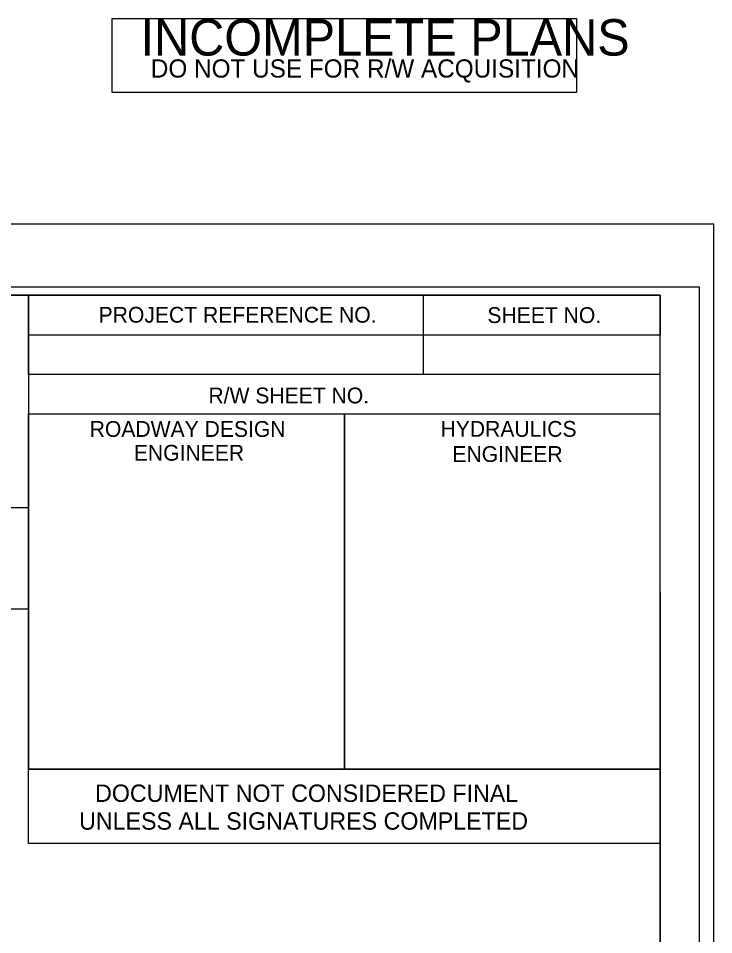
# Model space of a CAD drawing. Extents: x 2044275 to 2045958, y 759228 to 760388.
# Drawn here: x 2045738.1 to 2045958.4, y 760098.4 to 760388.4 of the extents above; entities that cross this region are included whole.
import ezdxf

# ---------------------------------------------------------------- set-up
doc = ezdxf.new("R2010")
doc.units = 0
for name, color, linetype in [('Old_Level_4', 7, 'Continuous'), ('Sheet Cutting Line CELL', 7, 'Continuous'), ('Sheet Plan CELL', 7, 'Continuous'), ('Sheet Plot Border Inside CELL', 7, 'Continuous'), ('Sheet Plot Border Outside CELL', 7, 'Continuous'), ('Sheet Sticker Exception Certification CELL', 7, 'Continuous'), ('Sheet Sticker Incomplete CELL', 7, 'Continuous')]:
    doc.layers.add(name, color=color, linetype=linetype)

msp = doc.modelspace()

# ---------------------------------------------------------------- linework, layer by layer
at = {"layer": 'Old_Level_4'}
for p, q in [((2045543.25, 760233.57), (2045741.31, 760233.57)), ((2045543.25, 760233.57), (2045741.31, 760233.57)), ((2045741.31, 760233.57), (2045741.31, 760201.37)), ((2045741.31, 760201.37), (2045543.25, 760201.37))]:
    msp.add_line(p, q, dxfattribs=at)
at = {"layer": 'Sheet Cutting Line CELL'}
msp.add_line((2045958.35, 760323.28), (2044274.85, 760323.28), dxfattribs=at)
at = {"layer": 'Sheet Plan CELL'}
for p, q in [((2045866.32, 760300.73), (2045866.37, 760275.73)), ((2045741.29, 760288.26), (2045941.34, 760288.25)), ((2045741.3, 760275.72), (2045941.34, 760275.75)), ((2045741.3, 760275.72), (2045941.34, 760275.75)), ((2045741.3, 760275.72), (2045741.3, 760263.23)), ((2045841.35, 760263.23), (2045841.37, 760150.77))]:
    msp.add_line(p, q, dxfattribs=at)
for points in [[(2044441.34, 759250.8), (2044441.32, 760300.77), (2045741.3, 760300.81), (2045741.32, 760150.75), (2045941.35, 760150.73), (2045941.35, 759250.8)], [(2045941.38, 760300.8), (2044441.34, 760300.8), (2044441.34, 759250.8), (2045941.35, 759250.8)], [(2045741.3, 760300.81), (2045941.38, 760300.8), (2045941.34, 760275.75), (2045741.3, 760275.72)], [(2045741.3, 760263.23), (2045841.35, 760263.23), (2045841.35, 760150.72), (2045741.32, 760150.75)], [(2045841.35, 760263.23), (2045941.34, 760263.25), (2045941.35, 760150.73), (2045841.35, 760150.72)]]:
    msp.add_lwpolyline(points, close=True, dxfattribs=at)
at = {"layer": 'Sheet Plot Border Inside CELL'}
msp.add_lwpolyline([(2044287.85, 759248.28), (2045953.84, 759248.3), (2045953.85, 760303.28), (2044287.85, 760303.28)], close=True, dxfattribs=at)
at = {"layer": 'Sheet Plot Border Outside CELL'}
msp.add_lwpolyline([(2044274.85, 759228.28), (2045958.35, 759228.28), (2045958.35, 760323.28), (2044274.85, 760323.28)], close=True, dxfattribs=at)
at = {"layer": 'Sheet Sticker Exception Certification CELL'}
for p, q in [((2045741.32, 760127.25), (2045741.32, 760150.75)), ((2045741.32, 760150.75), (2045941.35, 760150.75)), ((2045741.32, 760127.25), (2045741.32, 760150.75)), ((2045741.32, 760150.75), (2045941.35, 760150.75)), ((2045941.35, 760150.73), (2045941.35, 760127.23)), ((2045941.35, 760150.73), (2045941.35, 760127.23)), ((2045941.35, 760127.25), (2045741.32, 760127.25)), ((2045941.35, 760127.25), (2045741.32, 760127.25))]:
    msp.add_line(p, q, dxfattribs=at)
at = {"layer": 'Sheet Sticker Incomplete CELL'}
msp.add_lwpolyline([(2045767.85, 760364.9), (2045767.85, 760388.4), (2045914.85, 760388.4), (2045914.85, 760364.9)], close=True, dxfattribs=at)

# ---------------------------------------------------------------- texts
at = {"layer": 'Sheet Plan CELL'}
for s, height, p in [('PROJECT REFERENCE NO.', 5.0001, (2045763.5, 760292.08)), ('SHEET NO.', 5, (2045886.67, 760291.97)), ('R/W SHEET NO.', 5.0001, (2045798.3, 760266.53)), ('ROADWAY DESIGN', 5.0001, (2045760.68, 760255.93)), ('HYDRAULICS', 5, (2045871.82, 760255.96)), ('ENGINEER', 5, (2045774.67, 760248.4)), ('ENGINEER', 5, (2045875.58, 760248))]:
    msp.add_text(s, height=height, rotation=0, dxfattribs=at).set_placement(p)
at = {"layer": 'Sheet Sticker Exception Certification CELL'}
for s, p in [('DOCUMENT NOT CONSIDERED FINAL', (2045762.39, 760140.4)), ('DOCUMENT NOT CONSIDERED FINAL', (2045762.39, 760140.4)), ('UNLESS ALL SIGNATURES COMPLETED', (2045757.32, 760131.6)), ('UNLESS ALL SIGNATURES COMPLETED', (2045757.32, 760131.6))]:
    msp.add_text(s, height=5.5, dxfattribs=at).set_placement(p)
at = {"layer": 'Sheet Sticker Incomplete CELL'}
for s, height, p in [('INCOMPLETE PLANS', 11.52, (2045776.8, 760376.6)), ('DO NOT USE FOR R/W ACQUISITION', 5.76, (2045780.05, 760369.65))]:
    msp.add_text(s, height=height, dxfattribs=at).set_placement(p)

doc.saveas('drawing.dxf')
